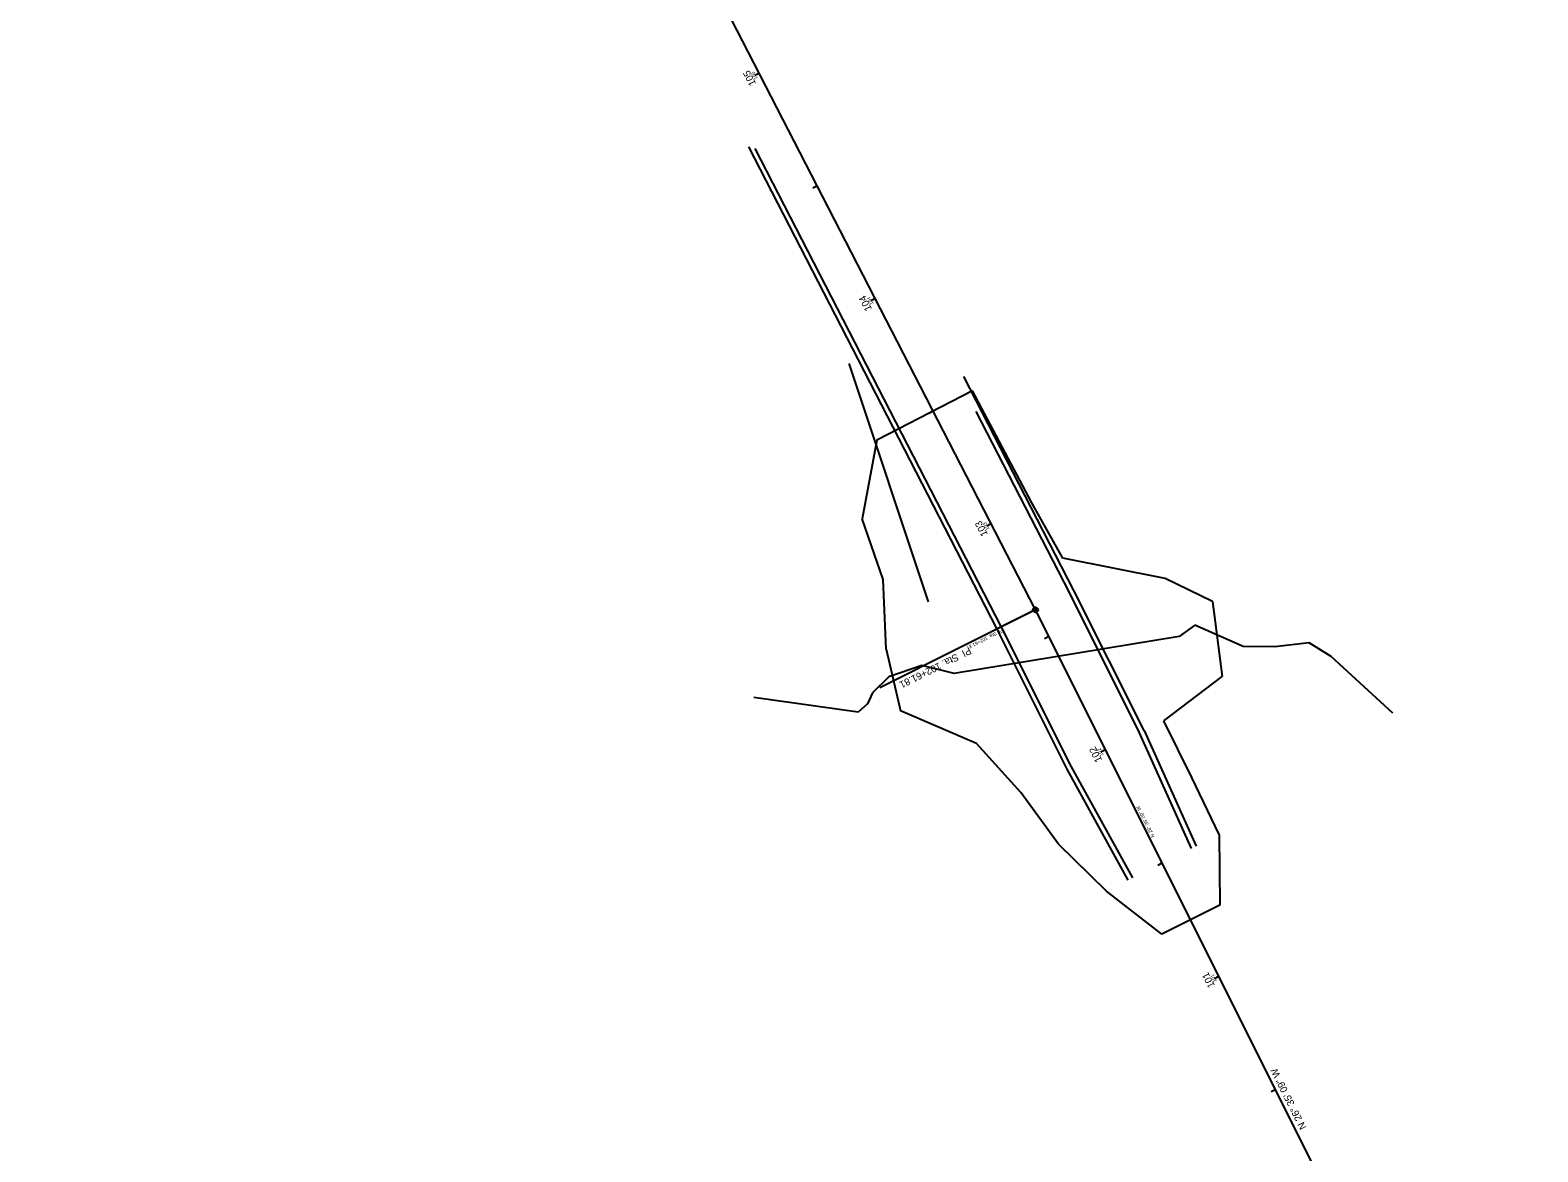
# Model space of a CAD drawing. Extents: x 1715640 to 1716553, y 394047 to 395910.
# Drawn here: x 1715853 to 1716448, y 394471 to 394914 of the extents above; entities that cross this region are included whole.
import ezdxf

# ---------------------------------------------------------------- set-up
doc = ezdxf.new("R2010")
doc.units = 0
for name, color, linetype in [('GE_P_CL_10', 7, 'Continuous'), ('GE_P_CL_20', 7, 'Continuous'), ('RW_P_Const_Limits', 7, 'Continuous'), ('SC_Scratch10', 7, 'Continuous'), ('UT_X_Water', 7, 'Continuous')]:
    doc.layers.add(name, color=color, linetype=linetype)

msp = doc.modelspace()

# ---------------------------------------------------------------- linework, layer by layer
at = {"layer": 'GE_P_CL_10'}
for p, q in [((1716249.46, 394685.42), (1715852.54, 395456.56)), ((1716140.45, 394897.2), (1716139.56, 394896.74)), ((1716163.33, 394852.75), (1716162.45, 394852.29)), ((1716186.22, 394808.29), (1716185.33, 394807.83)), ((1716209.1, 394763.83), (1716208.21, 394763.38)), ((1716231.98, 394719.38), (1716231.09, 394718.92)), ((1716249.01, 394685.2), (1716218.71, 394670.03)), ((1716447.81, 394289.08), (1716249.46, 394685.42)), ((1716254.75, 394674.86), (1716253.85, 394674.41)), ((1716277.12, 394630.15), (1716276.23, 394629.7)), ((1716299.5, 394585.43), (1716298.61, 394584.99)), ((1716321.88, 394540.72), (1716320.98, 394540.27)), ((1716344.25, 394496.01), (1716343.36, 394495.56))]:
    msp.add_line(p, q, dxfattribs=at)
msp.add_circle((1716249.46, 394685.42), 0.5, dxfattribs=at)
at = {"layer": 'GE_P_CL_20'}
for p, q in [((1716249.46, 394685.42), (1715852.54, 395456.56)), ((1716140.45, 394897.2), (1716138.67, 394896.29)), ((1716163.33, 394852.75), (1716161.56, 394851.83)), ((1716186.22, 394808.29), (1716184.44, 394807.37)), ((1716209.1, 394763.83), (1716207.32, 394762.92)), ((1716231.98, 394719.38), (1716230.2, 394718.46)), ((1716248.57, 394684.97), (1716187.95, 394654.64)), ((1716447.81, 394289.08), (1716249.46, 394685.42)), ((1716312.41, 394679.43), (1716306.2, 394674.83)), ((1716331.46, 394670.98), (1716312.41, 394679.43)), ((1716306.2, 394674.83), (1716217.39, 394660.23)), ((1716254.75, 394674.86), (1716252.96, 394673.96)), ((1716344.01, 394670.78), (1716331.46, 394670.98)), ((1716357.54, 394672.43), (1716344.01, 394670.78)), ((1716366.24, 394666.97), (1716357.54, 394672.43)), ((1716390.54, 394644.65), (1716366.24, 394666.97)), ((1716191.55, 394658.93), (1716185.11, 394652.62)), ((1716204.53, 394663.42), (1716191.55, 394658.93)), ((1716217.39, 394660.23), (1716204.53, 394663.42)), ((1716185.11, 394652.62), (1716183.12, 394648.26)), ((1716179.42, 394645.09), (1716138.32, 394650.75)), ((1716183.12, 394648.26), (1716179.42, 394645.09)), ((1716277.12, 394630.15), (1716275.33, 394629.25)), ((1716299.5, 394585.43), (1716297.71, 394584.54)), ((1716321.88, 394540.72), (1716320.09, 394539.82)), ((1716344.25, 394496.01), (1716342.46, 394495.11))]:
    msp.add_line(p, q, dxfattribs=at)
msp.add_circle((1716249.46, 394685.42), 1, dxfattribs=at)
at = {"layer": 'RW_P_Const_Limits'}
for p, q in [((1716224.58, 394771.8), (1716186.87, 394752.39)), ((1716248.06, 394727.65), (1716224.58, 394771.8)), ((1716186.87, 394752.39), (1716181.06, 394721.28)), ((1716260.2, 394705.78), (1716248.06, 394727.65)), ((1716189.3, 394697.4), (1716181.06, 394721.28)), ((1716300.68, 394697.85), (1716260.2, 394705.78)), ((1716190.53, 394669.92), (1716189.3, 394697.4)), ((1716319.3, 394688.72), (1716300.68, 394697.85)), ((1716319.3, 394688.72), (1716323.14, 394659.1)), ((1716190.53, 394669.92), (1716196.16, 394645.54)), ((1716300.15, 394641.67), (1716323.14, 394659.1)), ((1716311.19, 394619.24), (1716300.15, 394641.67)), ((1716321.98, 394596.68), (1716311.19, 394619.24)), ((1716258.56, 394592.9), (1716243.63, 394613.38)), ((1716277.45, 394574.4), (1716258.56, 394592.9)), ((1716321.98, 394596.68), (1716322.28, 394568.88)), ((1716299.37, 394557.41), (1716277.45, 394574.4)), ((1716322.28, 394568.88), (1716299.37, 394557.41))]:
    msp.add_line(p, q, dxfattribs=at)
msp.add_lwpolyline([(1716243.63, 394613.38), (1716226.2, 394632.62), (1716196.16, 394645.54)], dxfattribs=at)
at = {"layer": 'SC_Scratch10'}
for p, q in [((1716234.3, 394677.73), (1716136.28, 394868.17)), ((1716236.08, 394678.63), (1716138.85, 394867.54)), ((1716264.62, 394693.11), (1716221.14, 394777.58)), ((1716262.84, 394692.21), (1716226.03, 394763.72)), ((1716290.54, 394636.86), (1716262.84, 394692.21)), ((1716292.33, 394637.75), (1716264.62, 394693.11)), ((1716261.92, 394622.54), (1716234.3, 394677.73)), ((1716263.71, 394623.43), (1716236.08, 394678.63)), ((1716311.12, 394591.25), (1716290.54, 394636.86)), ((1716292.33, 394637.75), (1716312.91, 394592.15)), ((1716286.09, 394578.72), (1716261.92, 394622.54)), ((1716287.87, 394579.61), (1716263.71, 394623.43))]:
    msp.add_line(p, q, dxfattribs=at)
at = {"layer": 'UT_X_Water'}
msp.add_line((1716207.16, 394688.55), (1716175.85, 394782.59), dxfattribs=at)

# ---------------------------------------------------------------- texts
at = {"layer": 'GE_P_CL_10'}
for s, rotation, p in [('105', 117.23573, (1716139.82, 394895.15)), ('104', 117.23573, (1716185.58, 394806.25)), ('103', 117.23573, (1716231.36, 394717.32)), ('PI  Sta. 102+61.81', 206.58573, (1716236.36, 394678.08)), ('102', 116.58573, (1716276.46, 394628.11)), ('N 26%%d 35\' 09" W', 116.58573, (1716296.59, 394595.95)), ('101', 116.58573, (1716321.11, 394538.89))]:
    msp.add_text(s, height=1.4, rotation=rotation, dxfattribs=at).set_placement(p)
at = {"layer": 'GE_P_CL_20'}
for s, rotation, p in [('105', 117.23573, (1716139.19, 394893.1)), ('104', 117.23573, (1716184.94, 394804.21)), ('103', 117.23573, (1716230.73, 394715.26)), ('PI  Sta. 102+61.81', 206.58573, (1716223.26, 394670.74)), ('102', 116.58573, (1716275.81, 394626.07)), ('101', 116.58573, (1716320.35, 394537.06)), ('N 26%%d 35\' 09" W', 116.58573, (1716356.51, 394481.14))]:
    msp.add_text(s, height=2.8, rotation=rotation, dxfattribs=at).set_placement(p)

doc.saveas('drawing.dxf')
